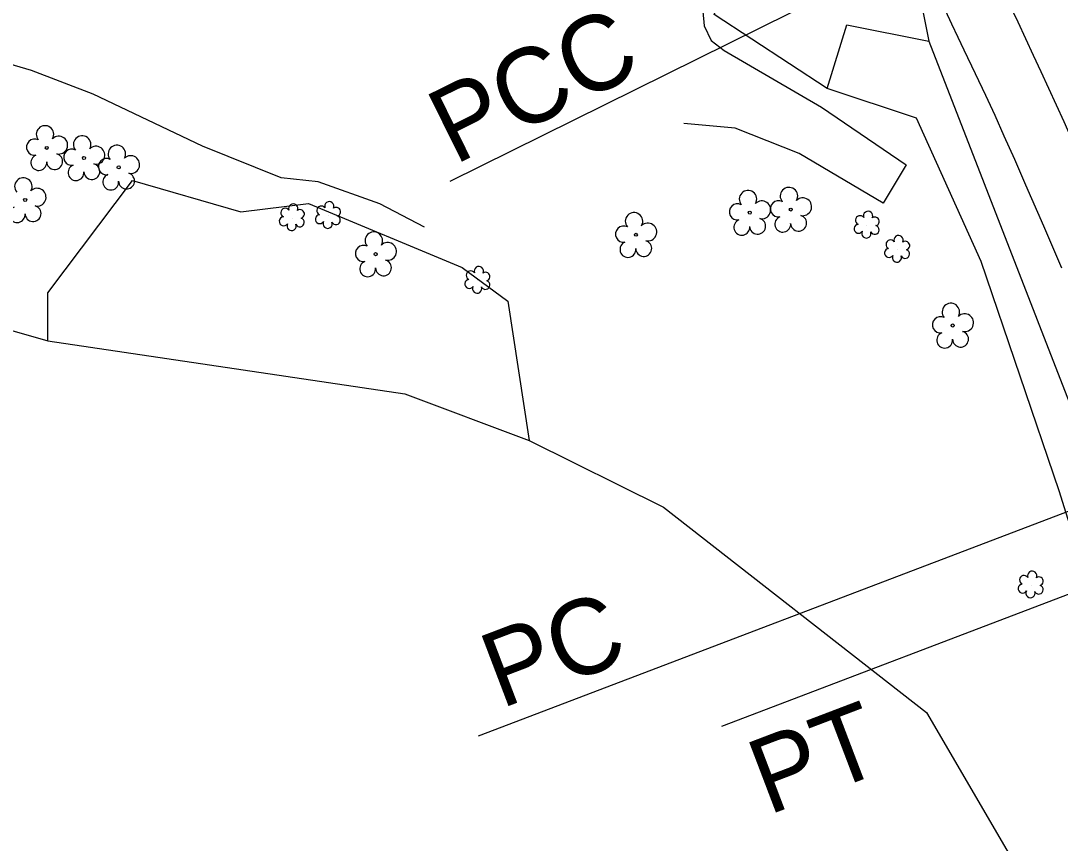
# Model space of a CAD drawing. Extents: x 471894 to 476235, y 503501 to 507878.
# Drawn here: x 474140.1 to 474361.6, y 505090.4 to 505265.7 of the extents above; entities that cross this region are included whole.
import ezdxf

# ---------------------------------------------------------------- set-up
doc = ezdxf.new("R2010")
doc.units = 0
for name, color, linetype in [('Exist Horizontal Alignment', 7, 'Continuous'), ('Exist Roads EOP', 7, 'Continuous'), ('Exist Roads EOP Other', 7, 'Continuous'), ('Exist Vegetation Hedge Row', 7, 'Continuous'), ('Exist Vegetation Shrub CELL', 7, 'Continuous'), ('Exist Vegetation Tree CELL', 7, 'Continuous'), ('Exist Vegetation Woods Line', 7, 'Continuous')]:
    doc.layers.add(name, color=color, linetype=linetype)

msp = doc.modelspace()

# ---------------------------------------------------------------- linework, layer by layer
at = {"layer": 'Exist Horizontal Alignment'}
for p, q in [((474339.07, 505284.76), (474231.53, 505231.46)), ((474388.86, 505170.83), (474237.56, 505113.21)), ((474394.73, 505155.4), (474289.39, 505115.29))]:
    msp.add_line(p, q, dxfattribs=at)
msp.add_arc((473181.76, 504711.19), 1295.4, 20.84556, 26.36313, dxfattribs=at)
at = {"layer": 'Exist Roads EOP'}
msp.add_lwpolyline([(474361.95, 505212.97), (474360.68, 505215.95), (474359.4, 505218.92), (474358.11, 505221.89), (474356.82, 505224.85), (474355.54, 505227.77), (474354.3, 505230.62), (474351.91, 505236.1), (474349.7, 505241.12), (474347.73, 505245.49), (474345.76, 505249.74), (474343.55, 505254.36), (474341.13, 505259.42), (474339.84, 505262.12), (474338.5, 505264.94), (474337.13, 505267.84)], dxfattribs=at)
at = {"layer": 'Exist Roads EOP Other'}
for points in [[(474255.2, 505347.88), (474262.34, 505326.27), (474268.91, 505307.01), (474272.6, 505297.55), (474282.7, 505281.77), (474287.12, 505273.12), (474286.07, 505270.82), (474285.47, 505267.68), (474285.75, 505264.57), (474287.25, 505261.46), (474289.99, 505259.33), (474310.71, 505247.24), (474328.8, 505234.96), (474323.9, 505226.78), (474305.98, 505237.39), (474292.34, 505242.83), (474281.37, 505243.82)], [(474226.1, 505221.68), (474216.61, 505226.69), (474203.48, 505231.36), (474195.56, 505232.23), (474178.78, 505238.94), (474155.51, 505250.06), (474142.38, 505255.07), (474123.42, 505260.64), (474115.58, 505264.49), (474122.26, 505277.08)]]:
    msp.add_lwpolyline(points, dxfattribs=at)
at = {"layer": 'Exist Vegetation Hedge Row'}
for points in [[(474311.95, 505251.22), (474287.89, 505267.03), (474293.69, 505278.83), (474302.08, 505282.03), (474310.58, 505275.45), (474325.97, 505276.84), (474331.58, 505271.74), (474333.63, 505261.37)], [(474145.85, 505197.49), (474145.85, 505207.71), (474163.9, 505231.65), (474186.95, 505224.95), (474201.36, 505226.77), (474234.17, 505213.07), (474243.88, 505205.91), (474248.45, 505176.22)]]:
    msp.add_lwpolyline(points, dxfattribs=at)
at = {"layer": 'Exist Vegetation Shrub CELL'}
for p, q in [((474205.6, 505224.11), (474205.6, 505224.11)), ((474197.92, 505223.64), (474197.92, 505223.64)), ((474320.43, 505222.05), (474320.43, 505222.05)), ((474326.93, 505216.9), (474326.93, 505216.9)), ((474237.47, 505210.29), (474237.47, 505210.29)), ((474355.41, 505145.37), (474355.41, 505145.37))]:
    msp.add_line(p, q, dxfattribs=at)
for centre, radius, start, end in [((474198.15, 505225.68), 0.99, 334.8391, 200.4717), ((474204.12, 505225.24), 0.968, 35.8908, 245.4216), ((474205.83, 505226.15), 0.99, 334.8391, 200.4717), ((474196.12, 505222.94), 0.955, 95.1099, 327.9534), ((474196.44, 505224.77), 0.968, 35.8908, 245.4216), ((474199.59, 505224.51), 0.929, 284.4567, 126.0861), ((474203.8, 505223.41), 0.955, 95.1099, 327.9534), ((474207.24, 505223.18), 0.937, 204.9913, 73.4601), ((474207.28, 505224.98), 0.929, 284.4567, 126.0861), ((474318.95, 505223.18), 0.968, 35.8908, 245.4216), ((474320.66, 505224.09), 0.99, 334.8391, 200.4717), ((474197.79, 505221.96), 0.984, 151.2797, 21.387), ((474199.56, 505222.71), 0.937, 204.9913, 73.4601), ((474205.48, 505222.43), 0.984, 151.2797, 21.387), ((474318.63, 505221.35), 0.955, 95.1099, 327.9534), ((474322.07, 505221.12), 0.937, 204.9913, 73.4601), ((474322.1, 505222.92), 0.929, 284.4567, 126.0861), ((474320.3, 505220.37), 0.984, 151.2797, 21.387), ((474327.16, 505218.94), 0.99, 334.8391, 200.4717), ((474325.45, 505218.03), 0.968, 35.8908, 245.4216), ((474328.61, 505217.77), 0.929, 284.4567, 126.0861), ((474325.13, 505216.2), 0.955, 95.1099, 327.9534), ((474326.81, 505215.22), 0.984, 151.2797, 21.387), ((474328.57, 505215.98), 0.937, 204.9913, 73.4601), ((474237.7, 505212.33), 0.99, 334.8391, 200.4717), ((474235.99, 505211.42), 0.968, 35.8908, 245.4216), ((474239.14, 505211.16), 0.929, 284.4567, 126.0861), ((474235.67, 505209.59), 0.955, 95.1099, 327.9534), ((474237.34, 505208.61), 0.984, 151.2797, 21.387), ((474239.11, 505209.37), 0.937, 204.9913, 73.4601), ((474353.93, 505146.5), 0.968, 35.8908, 245.4216), ((474355.64, 505147.41), 0.99, 334.8391, 200.4717), ((474357.09, 505146.24), 0.929, 284.4567, 126.0861), ((474353.61, 505144.67), 0.955, 95.1099, 327.9534), ((474355.29, 505143.69), 0.984, 151.2797, 21.387), ((474357.05, 505144.44), 0.937, 204.9913, 73.4601)]:
    msp.add_arc(centre, radius, start, end, dxfattribs=at)
at = {"layer": 'Exist Vegetation Tree CELL'}
for p, q in [((474145.61, 505238.59), (474145.61, 505238.59)), ((474153.53, 505236.45), (474153.53, 505236.45)), ((474160.94, 505234.44), (474160.94, 505234.44)), ((474141, 505227.49), (474141, 505227.49)), ((474295.45, 505224.8), (474295.45, 505224.8)), ((474304.18, 505225.45), (474304.18, 505225.45)), ((474271.17, 505220.07), (474271.17, 505220.07)), ((474215.7, 505215.94), (474215.7, 505215.94)), ((474338.7, 505200.74), (474338.7, 505200.74))]:
    msp.add_line(p, q, dxfattribs=at)
for centre in [(474145.61, 505238.59), (474153.53, 505236.45), (474160.94, 505234.44), (474141, 505227.49), (474295.45, 505224.8), (474304.18, 505225.45), (474271.17, 505220.07), (474215.7, 505215.94), (474338.7, 505200.74)]:
    msp.add_circle(centre, 0.326, dxfattribs=at)
for centre, radius, start, end in [((474145.23, 505241.47), 1.86, 330.1651, 219.7134), ((474143.01, 505238.75), 1.73, 62.6636, 279.3457), ((474148.16, 505239.18), 1.9, 257.1011, 134.1999), ((474153.15, 505239.32), 1.86, 330.1651, 219.7134), ((474147.29, 505235.69), 1.7, 181.2822, 74.56), ((474150.93, 505236.6), 1.73, 62.6636, 279.3457), ((474156.08, 505237.04), 1.9, 257.1011, 134.1999), ((474160.55, 505237.31), 1.86, 330.1651, 219.7134), ((474143.91, 505235.47), 1.69, 111.5671, 6.231), ((474155.21, 505233.55), 1.7, 181.2822, 74.56), ((474158.33, 505234.59), 1.73, 62.6636, 279.3457), ((474163.49, 505235.03), 1.9, 257.1011, 134.1999), ((474151.83, 505233.33), 1.69, 111.5671, 6.231), ((474159.24, 505231.32), 1.69, 111.5671, 6.231), ((474162.61, 505231.54), 1.7, 181.2822, 74.56), ((474140.62, 505230.36), 1.86, 330.1651, 219.7134), ((474143.55, 505228.08), 1.9, 257.1011, 134.1999), ((474295.07, 505227.67), 1.86, 330.1651, 219.7134), ((474303.8, 505228.32), 1.86, 330.1651, 219.7134), ((474142.68, 505224.59), 1.7, 181.2822, 74.56), ((474292.84, 505224.95), 1.73, 62.6636, 279.3457), ((474298, 505225.39), 1.9, 257.1011, 134.1999), ((474301.58, 505225.61), 1.73, 62.6636, 279.3457), ((474306.73, 505226.04), 1.9, 257.1011, 134.1999), ((474139.3, 505224.37), 1.69, 111.5671, 6.231), ((474270.78, 505222.94), 1.86, 330.1651, 219.7134), ((474302.48, 505222.33), 1.69, 111.5671, 6.231), ((474305.86, 505222.55), 1.7, 181.2822, 74.56), ((474268.56, 505220.22), 1.73, 62.6636, 279.3457), ((474273.72, 505220.66), 1.9, 257.1011, 134.1999), ((474293.75, 505221.68), 1.69, 111.5671, 6.231), ((474297.12, 505221.9), 1.7, 181.2822, 74.56), ((474215.32, 505218.82), 1.86, 330.1651, 219.7134), ((474213.1, 505216.1), 1.73, 62.6636, 279.3457), ((474218.25, 505216.53), 1.9, 257.1011, 134.1999), ((474269.47, 505216.95), 1.69, 111.5671, 6.231), ((474272.84, 505217.17), 1.7, 181.2822, 74.56), ((474214, 505212.82), 1.69, 111.5671, 6.231), ((474217.37, 505213.05), 1.7, 181.2822, 74.56), ((474338.31, 505203.62), 1.86, 330.1651, 219.7134), ((474336.09, 505200.9), 1.73, 62.6636, 279.3457), ((474341.24, 505201.33), 1.9, 257.1011, 134.1999), ((474336.99, 505197.62), 1.69, 111.5671, 6.231), ((474340.37, 505197.84), 1.7, 181.2822, 74.56)]:
    msp.add_arc(centre, radius, start, end, dxfattribs=at)
at = {"layer": 'Exist Vegetation Woods Line'}
for points in [[(474333.63, 505261.37), (474391.56, 505112.22), (474416.96, 505035.11), (474404.23, 505030.66), (474383.08, 505096.38), (474361.36, 505165.52), (474344.78, 505214.38), (474331, 505244.92), (474311.95, 505251.22), (474316.11, 505264.81), (474333.63, 505261.37)], [(474039.74, 505231.39), (474070.64, 505227.57), (474100.38, 505210.48), (474145.85, 505197.49), (474221.93, 505186.17), (474248.45, 505176.22), (474277.09, 505162.04), (474333.09, 505118.27), (474352.71, 505084.66), (474349.72, 505047.44), (474370.59, 505001.39), (474331.17, 504970.24), (474311.76, 504935.08), (474292.73, 504879.6), (474286.83, 504842.4), (474281, 504828.7), (474253.76, 504800.95), (474212.37, 504772.4), (474185.95, 504758.02), (474194.18, 504746.5), (474168.72, 504709.09), (474147.17, 504667.02), (474132.12, 504653.24), (474125.76, 504660.6)]]:
    msp.add_lwpolyline(points, dxfattribs=at)

# ---------------------------------------------------------------- texts
at = {"layer": 'Exist Horizontal Alignment'}
for s, rotation, p in [('PCC', 26.3631, (474232.52, 505234.87)), ('PC', 20.8456, (474242.38, 505119.01)), ('PT', 20.8456, (474299.38, 505096.32))]:
    msp.add_text(s, height=16, rotation=rotation, dxfattribs=at).set_placement(p)

doc.saveas('drawing.dxf')
